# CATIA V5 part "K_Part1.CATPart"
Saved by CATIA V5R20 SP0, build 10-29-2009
Part number: Part1
Bounding box of the stored display mesh (mm): x -53 to 53, y -400 to 256.561, z -87.225 to 0
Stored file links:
  G:\Khaled_CFAO_2011\ST2M\ST2M_GR2\amorin\Khaled\CAD_Modification\K_Part1.CATPart
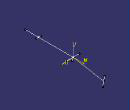
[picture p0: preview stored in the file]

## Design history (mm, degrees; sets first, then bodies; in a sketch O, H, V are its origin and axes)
Parameters
  `Angle.Tige-Corps` = 10 deg
  Longueur.Tige.Int = 300 mm
  Longueur.Tige.Ext = 300 mm
  Longueur.Tige.Sortie = 100 mm
Body1 (main body)
  Sketch1 on xy-plane, origin (0, 0, 0), H (1, 0, 0), V (0, 1, 0)
    line L1 (0, 0) -> (0, -400)
    line L2 (0, -291) -> (20, -291)
    point P2 (0, -291)
    point P3 (20, -291)
    point P4 (-20, -291)
    point P5 (0, -291)
    line L3 (0, -291) -> (-20, -291)
    line L4 (0, -5) -> (53, -5)
    point P6 (0, -5)
    point P7 (53, -5)
    point P8 (-53, -5)
    point P9 (0, -5)
    line L5 (0, -5) -> (-53, -5)
    length L1 = 400 {= Longueur.Tige.Ext +Longueur.Tige.Sortie}
    distance H L2 = 291 {= Longueur.Tige.Ext -9mm}
    distance L4 H = 5
    vertical: L1 V
    coincidence: P2 L1, P6 L1
    horizontal: L2 H, L4 H
    symmetry: P3 P4 L1, P2 P5 L1, L2 L3 L1, P7 P8 L1, P6 P9 L1, L4 L5 L1
  Sketch2 on yz-plane, origin (0, 0, 0), H (0, 1, 0), V (0, 0, 1)
    line L1 (-5, 0) -> (249.0804, -44.8012)
    point P1 (-5, 0)
    point P2 (249.0804, -44.8012)
    line L2 (-5, 0) -> (-10.3464, -30.3207)
    reference projected line E1 (0, 0) -> (-400, 0) from Sketch1.L1
    line L3 (249.0804, -44.8012) -> (256.5609, -2.377)
    point P4 (256.5609, -2.377)
    point P5 (241.5999, -87.2255)
    point P6 (249.0804, -44.8012)
    line L4 (249.0804, -44.8012) -> (241.5999, -87.2255)
    angle E1 L1 = 10 {= `Angle.Tige-Corps`}
    coincidence: P1 H
    perpendicularity: L2 L1, L3 L1
    symmetry: P4 P5 L1, P2 P6 L1, L3 L4 L1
